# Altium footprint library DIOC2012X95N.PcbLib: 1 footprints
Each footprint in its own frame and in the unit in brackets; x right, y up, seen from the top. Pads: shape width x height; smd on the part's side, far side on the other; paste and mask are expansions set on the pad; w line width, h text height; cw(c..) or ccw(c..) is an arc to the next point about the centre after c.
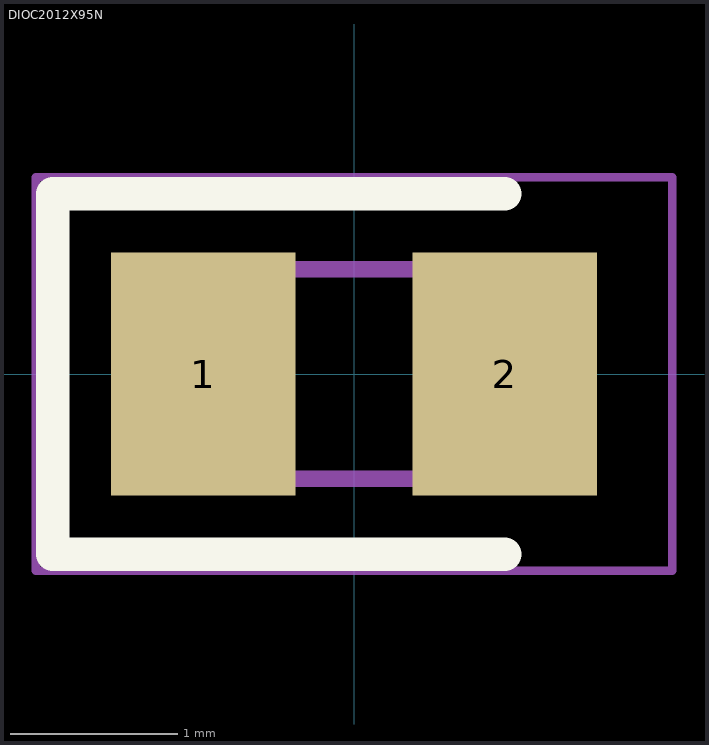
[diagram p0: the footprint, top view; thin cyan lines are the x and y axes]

## DIOC2012X95N [mm]
pads (2):
  rect 1.1x1.45 smd: 1(-0.9,0) 2(0.9,0)
Top Overlay:
  lines w0.2: 0.9,-1.075 -1.8,-1.075 -1.8,1.075 0.9,1.075
Mechanical 15:
  lines w0.1: -1,0.075 -0.45,0.625 ; -1,-0.625 1,-0.625 1,0.625 -1,0.625 -1,-0.625
Mechanical 20:
  lines w0.05: -1.9,-1.175 1.9,-1.175 1.9,1.175 -1.9,1.175 -1.9,-1.175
